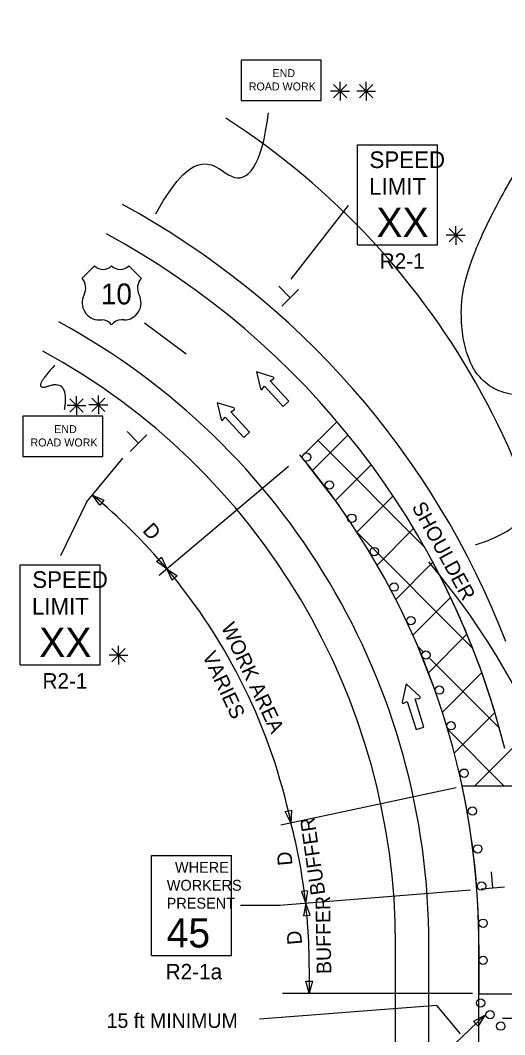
# Model space of a CAD drawing. Extents: x 16728 to 19504, y 5553 to 7079.
# Drawn here: x 16727.7 to 16960.2, y 6392 to 6878.4 of the extents above; entities that cross this region are included whole.
import ezdxf

# ---------------------------------------------------------------- set-up
doc = ezdxf.new("R2010")
doc.units = 0
for name, color, linetype in [('ALI_LEGAL_EX', 7, 'Continuous'), ('Level 3', 7, 'Continuous'), ('MT_SCRATCH_LEVEL_A', 7, 'Continuous'), ('MT_SCRATCH_LEVEL_E', 7, 'Continuous'), ('PAVT_EDGE_EX', 7, 'Continuous'), ('TRAFFIC_SIGNS_PR', 7, 'Continuous'), ('TYPICAL_EX', 7, 'Continuous'), ('TYPICAL_TEXT_DIMEN_PR', 7, 'Continuous')]:
    doc.layers.add(name, color=color, linetype=linetype)

msp = doc.modelspace()

# ---------------------------------------------------------------- linework, layer by layer
at = {"layer": 'ALI_LEGAL_EX'}
msp.add_line((16947.82, 6158.38), (16947.82, 6435.06), dxfattribs=at)
for points in [[(16807.35, 6718.27), (16787.33, 6733.25)], [(16880.88, 6645.61), (16865.54, 6665.36)], [(16926.92, 6556.59), (16917.84, 6579.89)]]:
    msp.add_lwpolyline(points, dxfattribs=at)
for centre, end in [((16629.65, 6525.15), 57.2958), ((16583.82, 6435.06), 40.1909), ((16645.75, 6383.76), 40.1909)]:
    msp.add_arc(centre, 364, 0, end, dxfattribs=at)
at = {"layer": 'Level 3'}
msp.add_line((16943.79, 6461.35), (16852.15, 6453.95), dxfattribs=at)
at = {"layer": 'MT_SCRATCH_LEVEL_A'}
for p, q in [((16862.64, 6669.01), (16879.71, 6686.08)), ((16867.96, 6662.56), (16885.03, 6679.63)), ((16921.62, 6625.93), (16870.81, 6676.74)), ((16878.96, 6648.1), (16896.13, 6665.28)), ((16889.3, 6632.99), (16906.63, 6650.32)), ((16944.81, 6577.29), (16889.65, 6632.44)), ((16898.97, 6617.2), (16916.49, 6634.73)), ((16907.94, 6600.72), (16925.71, 6618.49)), ((16916.17, 6583.5), (16934.26, 6601.59)), ((16923.64, 6565.51), (16942.1, 6583.97)), ((16921.08, 6575.56), (16918.53, 6578.11)), ((16957.63, 6539.01), (16923.9, 6572.73)), ((16930.28, 6546.69), (16949.19, 6565.61)), ((16945.7, 6511.2), (16996.34, 6561.84)), ((16936.02, 6526.98), (16955.48, 6546.44)), ((16959.98, 6511.2), (16932.86, 6538.32))]:
    msp.add_line(p, q, dxfattribs=at)
msp.add_arc((16583.82, 6435.06), 388, 14.0483, 28.2673, dxfattribs=at)
msp.add_arc((16583.82, 6435.06), 388, 14.0483, 28.2673, dxfattribs=at)
at = {"layer": 'MT_SCRATCH_LEVEL_E'}
for p, q in [((16849.09, 6707.3), (16841.13, 6709.83)), ((16841.13, 6709.83), (16843, 6701.71)), ((16847.67, 6705.5), (16849.19, 6706.47)), ((16856.64, 6695.73), (16847.67, 6705.5)), ((16843.82, 6701.53), (16844.92, 6702.97)), ((16844.92, 6702.97), (16853.88, 6693.2)), ((16830.19, 6692.5), (16822.24, 6695.03)), ((16822.24, 6695.03), (16824.11, 6686.92)), ((16853.88, 6693.2), (16856.64, 6695.73)), ((16828.78, 6690.7), (16830.3, 6691.67)), ((16837.74, 6680.94), (16828.78, 6690.7)), ((16824.92, 6686.74), (16826.02, 6688.17)), ((16826.02, 6688.17), (16834.99, 6678.41)), ((16834.99, 6678.41), (16837.74, 6680.94))]:
    msp.add_line(p, q, dxfattribs=at)
for centre, start, end in [((16848.94, 6706.86), 302.594, 72.331), ((16843.46, 6701.82), 192.9827, 322.5217), ((16830.04, 6692.06), 302.594, 72.331), ((16824.56, 6687.03), 192.9827, 322.5217)]:
    msp.add_arc(centre, 0.463, start, end, dxfattribs=at)
at = {"layer": 'PAVT_EDGE_EX'}
for p, q in [((16980.45, 6511.2), (16939.76, 6511.2)), ((16907.69, 6435.06), (16907.69, 6080.11)), ((16923.69, 6435.06), (16923.69, 6080.11)), ((16947.82, 6435.06), (16947.82, 6411.51)), ((16947.82, 6411.51), (16971.82, 6411.51))]:
    msp.add_line(p, q, dxfattribs=at)
for radius, start, end in [(404, 21.0961, 61.4862), (388, 14.0482, 61.4862), (340, 0, 61.4862), (324, 0, 61.4862), (364, 0, 12.0742)]:
    msp.add_arc((16583.82, 6435.06), radius, start, end, dxfattribs=at)
at = {"layer": 'TRAFFIC_SIGNS_PR'}
for p, q in [((16889.53, 6818.69), (16927.92, 6818.69)), ((16889.53, 6770.69), (16889.53, 6818.69)), ((16927.92, 6770.69), (16927.92, 6818.69)), ((16889.53, 6770.69), (16927.92, 6770.69)), ((16727.67, 6617.34), (16766.07, 6617.34)), ((16727.67, 6569.34), (16727.67, 6617.34)), ((16766.07, 6569.34), (16766.07, 6617.34)), ((16727.67, 6569.34), (16766.07, 6569.34)), ((16790.61, 6477.94), (16829.01, 6477.94)), ((16790.61, 6429.94), (16790.61, 6477.94)), ((16829.01, 6429.94), (16829.01, 6477.94)), ((16790.61, 6429.94), (16829.01, 6429.94))]:
    msp.add_line(p, q, dxfattribs=at)
for points in [[(16833.75, 6840.01), (16872.15, 6840.01), (16872.15, 6859.21), (16833.75, 6859.21)], [(16728.96, 6669.3), (16767.36, 6669.3), (16767.36, 6688.5), (16728.96, 6688.5)]]:
    msp.add_lwpolyline(points, close=True, dxfattribs=at)
for centre in [(16865.11, 6668.96), (16876.07, 6655.56), (16886.82, 6639.61), (16897.56, 6623.67), (16907.11, 6606.63), (16915.15, 6590.52), (16922.4, 6574.05), (16928.82, 6557.24), (16934.41, 6540.13), (16940.73, 6517.38), (16944.73, 6499.22), (16947.27, 6481.05), (16949.09, 6463.25), (16949.82, 6445.45), (16949.82, 6427.65), (16948.65, 6407.18), (16953.21, 6401.56), (16958.31, 6396.11)]:
    msp.add_circle(centre, 2, dxfattribs=at)
at = {"layer": 'TYPICAL_EX'}
for p, q in [((16757.38, 6754.75), (16763.27, 6760.64)), ((16785.67, 6754.75), (16779.78, 6760.64)), ((16765.62, 6734.69), (16766.8, 6734.69)), ((16777.43, 6734.69), (16776.25, 6734.69))]:
    msp.add_line(p, q, dxfattribs=at)
for centre, radius, start, end in [((16767.4, 6764.94), 5.96, 226.1404, 313.8596), ((16775.65, 6764.94), 5.96, 226.1404, 313.8596), ((16751.79, 6750.03), 7.31, 333.0977, 40.1936), ((16791.26, 6750.03), 7.31, 139.8064, 206.9023), ((16765.64, 6742.93), 8.24, 152.6698, 269.9013), ((16777.41, 6742.93), 8.24, 270.0987, 27.3302), ((16766.82, 6728.78), 5.91, 37.1038, 90.1385), ((16776.23, 6728.78), 5.91, 89.8615, 142.8962)]:
    msp.add_arc(centre, radius, start, end, dxfattribs=at)
at = {"layer": 'TYPICAL_TEXT_DIMEN_PR'}
for p, q in [((16881.18, 6844.39), (16876.65, 6844.39)), ((16877.99, 6847.58), (16884.37, 6841.2)), ((16884.37, 6847.58), (16877.99, 6841.2)), ((16881.18, 6844.39), (16881.18, 6848.84)), ((16881.18, 6844.39), (16884.37, 6844.39)), ((16881.18, 6844.39), (16885.66, 6844.39)), ((16881.18, 6844.39), (16881.18, 6839.89)), ((16893.74, 6844.39), (16889.2, 6844.39)), ((16890.55, 6847.58), (16896.93, 6841.2)), ((16896.93, 6847.58), (16890.55, 6841.2)), ((16893.74, 6844.39), (16893.74, 6848.84)), ((16893.74, 6844.39), (16896.93, 6844.39)), ((16893.74, 6844.39), (16898.22, 6844.39)), ((16893.74, 6844.39), (16893.74, 6839.89)), ((16857.64, 6754.19), (16885.3, 6789.55)), ((16939.9, 6778.49), (16933.52, 6772.11)), ((16933.53, 6778.49), (16939.9, 6772.11)), ((16936.71, 6775.3), (16936.71, 6779.76)), ((16936.71, 6775.3), (16932.18, 6775.3)), ((16936.71, 6775.3), (16939.9, 6775.3)), ((16936.71, 6775.3), (16941.19, 6775.3)), ((16936.71, 6775.3), (16936.71, 6770.8)), ((16857.24, 6745.35), (16851.73, 6750.84)), ((16861.21, 6749.33), (16853.27, 6741.36)), ((16765.15, 6693.98), (16765.15, 6698.44)), ((16754.68, 6693.72), (16750.15, 6693.72)), ((16751.49, 6696.91), (16757.87, 6690.53)), ((16757.87, 6696.91), (16751.49, 6690.53)), ((16754.68, 6693.72), (16754.68, 6698.18)), ((16754.68, 6693.72), (16757.87, 6693.72)), ((16754.68, 6693.72), (16759.16, 6693.72)), ((16754.68, 6693.72), (16754.68, 6689.22)), ((16765.15, 6693.98), (16760.61, 6693.98)), ((16761.96, 6697.17), (16768.33, 6690.79)), ((16768.33, 6697.17), (16761.96, 6690.79)), ((16765.15, 6693.98), (16768.33, 6693.98)), ((16765.15, 6693.98), (16769.62, 6693.98)), ((16765.15, 6693.98), (16765.15, 6689.48)), ((16784.43, 6675.69), (16778.92, 6681.19)), ((16788.4, 6679.68), (16780.46, 6671.71)), ((16759.53, 6647.38), (16776.91, 6668.37)), ((16759.53, 6647.38), (16776.91, 6668.37)), ((16794.39, 6612.39), (16856.44, 6664.65)), ((16765.85, 6645.82), (16762.34, 6650.77)), ((16762.34, 6650.77), (16767.85, 6648.24)), ((16759.53, 6647.38), (16746.92, 6621.6)), ((16766.85, 6647.03), (16765.85, 6645.82)), ((16767.85, 6648.24), (16766.85, 6647.03)), ((16794.21, 6619.9), (16795.41, 6620.91)), ((16795.41, 6620.91), (16797.99, 6615.42)), ((16793.01, 6618.89), (16794.21, 6619.9)), ((16797.99, 6615.42), (16793.01, 6618.89)), ((16800.56, 6609.92), (16797.99, 6615.42)), ((16797.99, 6615.42), (16802.97, 6611.95)), ((16801.76, 6610.94), (16800.56, 6609.92)), ((16802.97, 6611.95), (16801.76, 6610.94)), ((16771.67, 6577.15), (16778.04, 6570.77)), ((16778.04, 6577.15), (16771.67, 6570.77)), ((16774.85, 6573.96), (16774.85, 6578.41)), ((16774.85, 6573.96), (16770.32, 6573.96)), ((16774.85, 6573.96), (16778.04, 6573.96)), ((16774.85, 6573.96), (16779.33, 6573.96)), ((16774.85, 6573.96), (16774.85, 6569.46)), ((16912.94, 6560.16), (16911.03, 6551.49)), ((16919.44, 6554.09), (16912.94, 6560.16)), ((16917.26, 6553), (16919.17, 6553.24)), ((16921.44, 6539.49), (16917.26, 6553)), ((16911.74, 6550.94), (16913.45, 6551.82)), ((16913.45, 6551.82), (16917.63, 6538.31)), ((16917.63, 6538.31), (16921.44, 6539.49)), ((16852.73, 6492.58), (16936.83, 6510.57)), ((16854.86, 6499.03), (16856.4, 6499.36)), ((16857.62, 6493.63), (16854.86, 6499.03)), ((16856.4, 6499.36), (16857.93, 6499.69)), ((16857.93, 6499.69), (16857.62, 6493.63)), ((16954.46, 6462.26), (16953.83, 6470.02)), ((16864.21, 6460.81), (16862.65, 6460.68)), ((16862.65, 6460.68), (16864.69, 6454.96)), ((16865.78, 6460.93), (16864.21, 6460.81)), ((16864.69, 6454.96), (16865.78, 6460.93)), ((16960.06, 6462.72), (16948.85, 6461.8)), ((16852.15, 6453.95), (16833.36, 6453.95)), ((16864.69, 6454.96), (16863.66, 6448.98)), ((16866.79, 6449.27), (16864.69, 6454.96)), ((16863.66, 6448.98), (16865.23, 6449.13)), ((16865.23, 6449.13), (16866.79, 6449.27)), ((16866.39, 6424.09), (16866.39, 6411.86)), ((16866.39, 6411.86), (16864.82, 6417.72)), ((16864.82, 6417.72), (16866.39, 6417.72)), ((16866.39, 6417.72), (16867.96, 6417.72)), ((16867.96, 6417.72), (16866.39, 6411.86)), ((16853.56, 6411.86), (16944.76, 6411.86)), ((16927.68, 6406.05), (16842.47, 6399.49)), ((16939.03, 6392.35), (16927.68, 6406.05)), ((16950.66, 6401.27), (16928.11, 6379.97)), ((16945.32, 6398.39), (16950.66, 6401.27)), ((16946.4, 6397.25), (16945.32, 6398.39)), ((16947.48, 6396.11), (16946.4, 6397.25)), ((16950.66, 6401.27), (16947.48, 6396.11)), ((16970.43, 6399.68), (16959.18, 6399.68))]:
    msp.add_line(p, q, dxfattribs=at)
for centre, radius, start, end in [((16583.82, 6435.06), 280, 40.102, 50.3886), ((16583.82, 6435.06), 280, 12.0744, 40.102), ((16919.1, 6553.73), 0.494, 277.2371, 46.974), ((16911.52, 6551.39), 0.494, 167.6257, 297.1647), ((16586.39, 6424.09), 280, 6.3295, 14.379), ((16586.39, 6424.09), 280, 4.0506, 6.3295), ((16586.39, 6424.09), 280, 0, 4.0506)]:
    msp.add_arc(centre, radius, start, end, dxfattribs=at)
for points, degree in [([(16946.2, 6626.92), (16977.56, 6636.36), (16992.5, 6695.83), (16939.3, 6701.55), (16939.4, 6777.31), (17014.81, 6878.41)], 2), ([(16792.71, 6785.53), (16812.75, 6822.09), (16829.8, 6792), (16843.76, 6808.28), (16846.76, 6833.99)], 3), ([(16744.31, 6713.02), (16731.94, 6699.84), (16751.15, 6706.43), (16748.78, 6691.66)], 2)]:
    msp.add_open_spline(points, degree=degree, dxfattribs=at)

# ---------------------------------------------------------------- texts
at = {"layer": 'TRAFFIC_SIGNS_PR'}
for s, height, p in [('END', 3.831, (16848.75, 6851.14)), ('ROAD WORK', 3.831, (16837.36, 6844.76)), ('SPEED', 8, (16895.29, 6807.55)), ('LIMIT', 8, (16895.13, 6794.75)), ('XX', 14.031, (16898.64, 6774.45)), ('R2-1', 7.44, (16900.2, 6759.25)), ('END', 3.831, (16743.96, 6680.43)), ('ROAD WORK', 3.831, (16732.57, 6674.04)), ('SPEED', 8, (16733.43, 6606.21)), ('LIMIT', 8, (16733.27, 6593.41)), ('XX', 14.031, (16736.78, 6573.1)), ('R2-1', 7.44, (16738.34, 6557.9)), ('WHERE', 5.2, (16801.92, 6469.63)), ('WORKERS', 5.2, (16797.99, 6461.03)), ('PRESENT', 5.2, (16797.93, 6452.43)), ('45', 14.031, (16797.92, 6433.8)), ('R2-1a', 7.44, (16797.46, 6418.5))]:
    msp.add_text(s, height=height, dxfattribs=at).set_placement(p)
at = {"layer": 'TYPICAL_EX'}
msp.add_text('10', height=10, dxfattribs=at).set_placement((16766.37, 6742.17))
at = {"layer": 'TYPICAL_TEXT_DIMEN_PR'}
for s, rotation, p in [('SHOULDER', 298.6431, (16915.41, 6645.13)), ('D', 312.2189, (16786.01, 6633.51)), ('WORK AREA', 295.1762, (16823.91, 6587.55)), ('VARIES', 295.1762, (16814.91, 6573.77)), ('BUFFER', 98.1044, (16874.11, 6459.44)), ('D', 95.1476, (16858.37, 6473.36)), ('BUFFER', 91.0079, (16876.99, 6421.13)), ('D', 95.1476, (16862.99, 6435.43))]:
    msp.add_text(s, height=7, rotation=rotation, dxfattribs=at).set_placement(p)
msp.add_text('15 ft MINIMUM', height=7, dxfattribs=at).set_placement((16769.13, 6395.24))

doc.saveas('drawing.dxf')
